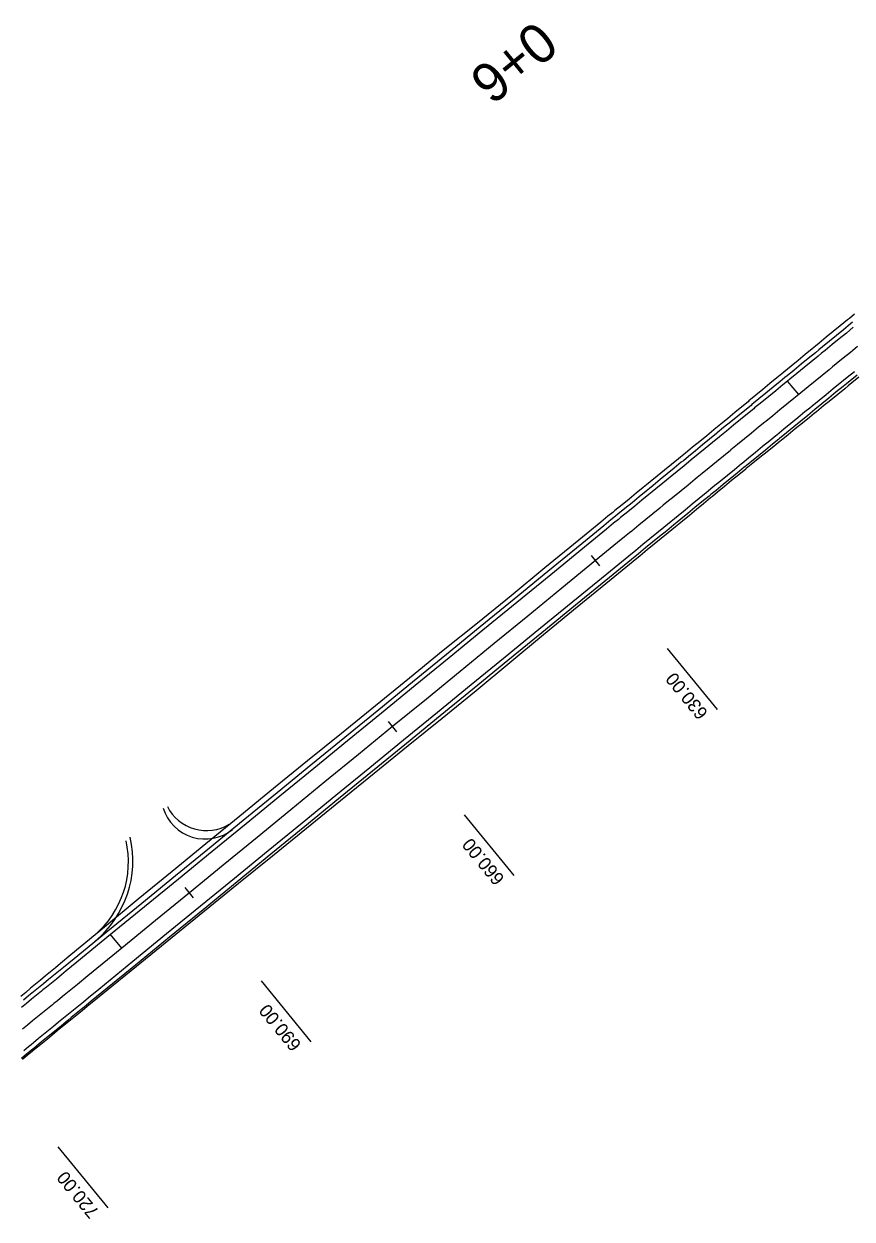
# Model space of a CAD drawing. Extents: x -550605 to -538780, y -1102367 to -1093705.
# Drawn here: x -547048.1 to -546953.4, y -1101076.3 to -1100939.6 of the extents above; entities that cross this region are included whole.
import ezdxf

# ---------------------------------------------------------------- set-up
doc = ezdxf.new("R2010")
doc.units = 0
for name, color, linetype in [('SIT - hrany vozovky', 7, 'Continuous'), ('SIT - oblouky - hrany', 7, 'Continuous'), ('SIT - oblouky - koruna', 7, 'Continuous'), ('SIT - osa cesty', 7, 'Continuous'), ('SIT - paty násypů', 7, 'Continuous'), ('SIT - staničení po 100m', 7, 'Continuous'), ('SIT - staničení po 30m', 7, 'Continuous')]:
    doc.layers.add(name, color=color, linetype=linetype)

msp = doc.modelspace()

# ---------------------------------------------------------------- linework, layer by layer
at = {"layer": 'SIT - hrany vozovky'}
for points in [[(-546953.35, -1100973.72), (-546953.57, -1100973.91), (-546954.38, -1100974.57), (-546955.19, -1100975.23), (-546955.99, -1100975.89), (-546956.8, -1100976.54), (-546957.22, -1100976.89), (-546957.6, -1100977.2), (-546958.41, -1100977.86), (-546959.22, -1100978.52), (-546960.02, -1100979.18), (-546960.83, -1100979.84), (-546961.09, -1100980.05), (-546961.64, -1100980.5), (-546962.44, -1100981.16), (-546963.25, -1100981.82), (-546964.06, -1100982.48), (-546964.86, -1100983.14), (-546964.96, -1100983.22), (-546965.67, -1100983.8), (-546966.47, -1100984.46), (-546967.28, -1100985.12), (-546968.09, -1100985.77), (-546968.83, -1100986.38), (-546968.89, -1100986.43), (-546969.7, -1100987.09), (-546970.51, -1100987.75), (-546971.31, -1100988.41), (-546972.12, -1100989.07), (-546972.7, -1100989.55), (-546972.93, -1100989.73), (-546973.73, -1100990.39), (-546974.54, -1100991.05), (-546975.34, -1100991.71), (-546976.15, -1100992.37), (-546976.57, -1100992.71), (-546976.96, -1100993.03), (-546977.76, -1100993.69), (-546978.57, -1100994.35), (-546979.38, -1100995), (-546980.18, -1100995.66), (-546980.44, -1100995.88), (-546980.99, -1100996.32), (-546981.8, -1100996.98), (-546984.31, -1100999.04), (-546988.18, -1101002.21), (-546992.05, -1101005.37), (-546995.93, -1101008.54), (-546999.8, -1101011.7), (-547003.67, -1101014.86), (-547007.54, -1101018.03), (-547011.41, -1101021.19), (-547015.28, -1101024.36), (-547019.15, -1101027.52), (-547023.02, -1101030.69), (-547026.89, -1101033.85), (-547030.76, -1101037.02), (-547034.63, -1101040.18), (-547038.51, -1101043.35), (-547042.38, -1101046.51), (-547043.58, -1101047.5), (-547044.15, -1101047.96), (-547044.72, -1101048.43), (-547045.29, -1101048.89), (-547045.86, -1101049.36), (-547046.25, -1101049.68), (-547046.43, -1101049.83), (-547047, -1101050.29), (-547047.57, -1101050.76), (-547048.14, -1101051.22)], [(-546953.26, -1100974.29), (-546954.06, -1100974.95), (-546954.87, -1100975.61), (-546955.68, -1100976.27), (-546956.48, -1100976.93), (-546956.9, -1100977.27), (-546957.29, -1100977.59), (-546958.09, -1100978.25), (-546958.9, -1100978.91), (-546959.71, -1100979.57), (-546960.51, -1100980.23), (-546960.77, -1100980.44), (-546961.32, -1100980.89), (-546962.13, -1100981.55), (-546962.93, -1100982.21), (-546963.74, -1100982.87), (-546964.55, -1100983.52), (-546964.64, -1100983.6), (-546965.35, -1100984.18), (-546966.16, -1100984.84), (-546966.96, -1100985.5), (-546967.77, -1100986.16), (-546968.51, -1100986.77), (-546968.58, -1100986.82), (-546969.38, -1100987.48), (-546970.19, -1100988.14), (-546971, -1100988.8), (-546971.8, -1100989.46), (-546972.38, -1100989.93), (-546972.61, -1100990.12), (-546973.42, -1100990.78), (-546974.22, -1100991.44), (-546975.03, -1100992.1), (-546975.83, -1100992.75), (-546976.25, -1100993.1), (-546976.64, -1100993.41), (-546977.45, -1100994.07), (-546978.25, -1100994.73), (-546979.06, -1100995.39), (-546979.87, -1100996.05), (-546980.13, -1100996.26), (-546980.67, -1100996.71), (-546981.48, -1100997.37), (-546984, -1100999.43), (-546987.87, -1101002.59), (-546991.74, -1101005.76), (-546995.61, -1101008.92), (-546999.48, -1101012.09), (-547003.35, -1101015.25), (-547007.22, -1101018.42), (-547011.09, -1101021.58), (-547014.96, -1101024.75), (-547018.83, -1101027.91), (-547022.71, -1101031.08), (-547026.58, -1101034.24), (-547030.45, -1101037.41), (-547034.32, -1101040.57), (-547038.19, -1101043.74), (-547042.06, -1101046.9), (-547043.27, -1101047.89), (-547043.83, -1101048.35), (-547044.4, -1101048.82), (-547044.97, -1101049.28), (-547045.54, -1101049.75), (-547045.93, -1101050.06), (-547046.11, -1101050.21), (-547046.68, -1101050.68), (-547047.25, -1101051.14), (-547047.82, -1101051.61), (-547048.39, -1101052.07)], [(-546953.14, -1100979.37), (-546953.95, -1100980.03), (-546954.37, -1100980.37), (-546954.76, -1100980.69), (-546955.56, -1100981.35), (-546956.37, -1100982.01), (-546957.18, -1100982.67), (-546957.98, -1100983.33), (-546958.24, -1100983.54), (-546958.79, -1100983.98), (-546959.59, -1100984.64), (-546960.4, -1100985.3), (-546961.21, -1100985.96), (-546962.01, -1100986.62), (-546962.11, -1100986.7), (-546962.82, -1100987.28), (-546963.63, -1100987.94), (-546964.43, -1100988.6), (-546965.24, -1100989.26), (-546965.98, -1100989.87), (-546966.05, -1100989.92), (-546966.85, -1100990.58), (-546967.66, -1100991.24), (-546968.46, -1100991.9), (-546969.27, -1100992.55), (-546969.85, -1100993.03), (-546970.08, -1100993.21), (-546970.88, -1100993.87), (-546971.69, -1100994.53), (-546972.5, -1100995.19), (-546973.3, -1100995.85), (-546973.72, -1100996.19), (-546974.11, -1100996.51), (-546974.92, -1100997.17), (-546975.72, -1100997.83), (-546976.53, -1100998.49), (-546977.33, -1100999.15), (-546977.59, -1100999.36), (-546978.14, -1100999.81), (-546978.95, -1101000.47), (-546981.46, -1101002.52), (-546985.34, -1101005.69), (-546989.21, -1101008.85), (-546993.08, -1101012.02), (-546996.95, -1101015.18), (-547000.82, -1101018.35), (-547004.69, -1101021.51), (-547008.56, -1101024.68), (-547012.43, -1101027.84), (-547016.3, -1101031.01), (-547020.17, -1101034.17), (-547024.04, -1101037.34), (-547027.92, -1101040.5), (-547031.79, -1101043.67), (-547035.66, -1101046.83), (-547039.53, -1101050), (-547040.73, -1101050.98), (-547041.3, -1101051.45), (-547041.87, -1101051.91), (-547042.44, -1101052.38), (-547043.01, -1101052.84), (-547043.4, -1101053.16), (-547043.58, -1101053.31), (-547044.15, -1101053.77), (-547044.72, -1101054.24), (-547045.29, -1101054.71), (-547045.86, -1101055.17), (-547046.43, -1101055.64), (-547047, -1101056.1), (-547047.27, -1101056.33), (-547047.57, -1101056.57), (-547048.13, -1101057.03)], [(-546952.83, -1100979.76), (-546953.63, -1100980.42), (-546954.05, -1100980.76), (-546954.44, -1100981.07), (-546955.25, -1100981.73), (-546956.05, -1100982.39), (-546956.86, -1100983.05), (-546957.67, -1100983.71), (-546957.92, -1100983.92), (-546958.47, -1100984.37), (-546959.28, -1100985.03), (-546960.08, -1100985.69), (-546960.89, -1100986.35), (-546961.7, -1100987.01), (-546961.79, -1100987.09), (-546962.5, -1100987.67), (-546963.31, -1100988.33), (-546964.12, -1100988.99), (-546964.92, -1100989.65), (-546965.66, -1100990.25), (-546965.73, -1100990.3), (-546966.54, -1100990.96), (-546967.34, -1100991.62), (-546968.15, -1100992.28), (-546968.95, -1100992.94), (-546969.54, -1100993.42), (-546969.76, -1100993.6), (-546970.57, -1100994.26), (-546971.37, -1100994.92), (-546972.18, -1100995.58), (-546972.99, -1100996.24), (-546973.41, -1100996.58), (-546973.79, -1100996.9), (-546974.6, -1100997.56), (-546975.41, -1100998.22), (-546976.21, -1100998.88), (-546977.02, -1100999.53), (-546977.28, -1100999.75), (-546977.82, -1101000.19), (-546978.63, -1101000.85), (-546981.15, -1101002.91), (-546985.02, -1101006.08), (-546988.89, -1101009.24), (-546992.76, -1101012.41), (-546996.63, -1101015.57), (-547000.5, -1101018.74), (-547004.37, -1101021.9), (-547008.24, -1101025.07), (-547012.12, -1101028.23), (-547015.99, -1101031.39), (-547019.86, -1101034.56), (-547023.73, -1101037.72), (-547027.6, -1101040.89), (-547031.47, -1101044.05), (-547035.34, -1101047.22), (-547039.21, -1101050.38), (-547040.42, -1101051.37), (-547040.99, -1101051.83), (-547041.56, -1101052.3), (-547042.12, -1101052.77), (-547042.69, -1101053.23), (-547043.08, -1101053.55), (-547043.26, -1101053.7), (-547043.83, -1101054.16), (-547044.4, -1101054.63), (-547044.97, -1101055.09), (-547045.54, -1101055.56), (-547046.11, -1101056.02), (-547046.68, -1101056.49), (-547046.95, -1101056.71), (-547047.25, -1101056.95), (-547047.82, -1101057.42), (-547048.39, -1101057.89)]]:
    msp.add_lwpolyline(points, dxfattribs=at)
at = {"layer": 'SIT - oblouky - hrany'}
for centre, radius, start, end in [((-547027.23, -1101026.85), 5, 206.5983, 301.3106), ((-547047.16, -1101035.44), 11, 310.5384, 12.8009)]:
    msp.add_arc(centre, radius, start, end, dxfattribs=at)
at = {"layer": 'SIT - oblouky - koruna'}
for centre, radius, start, end in [((-547027.39, -1101027.81), 5, 196.9978, 308.73), ((-547047.65, -1101035.29), 12, 309.9531, 12.8843)]:
    msp.add_arc(centre, radius, start, end, dxfattribs=at)
at = {"layer": 'SIT - osa cesty'}
msp.add_lwpolyline([(-546952.8, -1100976.5), (-546953.6, -1100977.16), (-546954.41, -1100977.82), (-546955.22, -1100978.48), (-546955.63, -1100978.82), (-546956.02, -1100979.14), (-546956.83, -1100979.8), (-546957.63, -1100980.46), (-546958.44, -1100981.12), (-546959.25, -1100981.78), (-546959.51, -1100981.99), (-546960.05, -1100982.44), (-546960.86, -1100983.1), (-546961.67, -1100983.75), (-546962.47, -1100984.41), (-546963.28, -1100985.07), (-546963.38, -1100985.15), (-546964.09, -1100985.73), (-546964.89, -1100986.39), (-546965.7, -1100987.05), (-546966.5, -1100987.71), (-546967.25, -1100988.32), (-546967.31, -1100988.37), (-546968.12, -1100989.03), (-546968.92, -1100989.69), (-546969.73, -1100990.35), (-546970.54, -1100991.01), (-546971.12, -1100991.48), (-546971.34, -1100991.67), (-546972.15, -1100992.33), (-546972.96, -1100992.98), (-546973.76, -1100993.64), (-546974.57, -1100994.3), (-546974.99, -1100994.65), (-546975.37, -1100994.96), (-546976.18, -1100995.62), (-546976.99, -1100996.28), (-546977.79, -1100996.94), (-546978.6, -1100997.6), (-546978.86, -1100997.81), (-546979.41, -1100998.26), (-546980.21, -1100998.92), (-546982.73, -1101000.98), (-546986.6, -1101004.14), (-546990.47, -1101007.31), (-546994.34, -1101010.47), (-546998.21, -1101013.64), (-547002.09, -1101016.8), (-547005.96, -1101019.96), (-547009.83, -1101023.13), (-547013.7, -1101026.29), (-547017.57, -1101029.46), (-547021.44, -1101032.62), (-547025.31, -1101035.79), (-547029.18, -1101038.95), (-547033.05, -1101042.12), (-547036.92, -1101045.28), (-547040.79, -1101048.45), (-547042, -1101049.43), (-547042.57, -1101049.9), (-547043.14, -1101050.36), (-547043.71, -1101050.83), (-547044.28, -1101051.3), (-547044.67, -1101051.61), (-547044.85, -1101051.76), (-547045.42, -1101052.23), (-547045.98, -1101052.69), (-547046.55, -1101053.16), (-547047.12, -1101053.62), (-547047.69, -1101054.09), (-547048.26, -1101054.55)], dxfattribs=at)
at = {"layer": 'SIT - paty násypů'}
for points in [[(-546953.14, -1100972.8), (-546953.71, -1100973.27), (-546953.94, -1100973.46), (-546954.75, -1100974.12), (-546955.55, -1100974.78), (-546956.36, -1100975.44), (-546957.16, -1100976.1), (-546957.58, -1100976.44), (-546957.97, -1100976.76), (-546958.77, -1100977.42), (-546959.58, -1100978.08), (-546960.38, -1100978.74), (-546961.19, -1100979.41), (-546961.44, -1100979.62), (-546961.99, -1100980.07), (-546962.79, -1100980.73), (-546963.6, -1100981.39), (-546964.4, -1100982.06), (-546965.2, -1100982.72), (-546965.3, -1100982.8), (-546966.01, -1100983.38), (-546966.81, -1100984.04), (-546967.61, -1100984.71), (-546968.42, -1100985.37), (-546969.16, -1100985.98), (-546969.22, -1100986.03), (-546970.03, -1100986.69), (-546970.83, -1100987.35), (-546971.64, -1100988.01), (-546972.45, -1100988.67), (-546973.03, -1100989.14), (-546973.26, -1100989.32), (-546974.07, -1100989.98), (-546974.87, -1100990.64), (-546975.68, -1100991.3), (-546976.49, -1100991.96), (-546976.91, -1100992.3), (-546977.29, -1100992.61), (-546978.1, -1100993.27), (-546978.91, -1100993.93), (-546979.71, -1100994.59), (-546980.52, -1100995.25), (-546980.78, -1100995.46), (-546981.33, -1100995.91), (-546982.13, -1100996.57), (-546984.65, -1100998.63), (-546988.52, -1101001.79), (-546992.37, -1101004.99), (-546996.25, -1101008.14), (-547000.15, -1101011.27), (-547004.03, -1101014.42), (-547007.91, -1101017.57), (-547011.79, -1101020.73), (-547015.67, -1101023.88), (-547019.55, -1101027.04), (-547023.42, -1101030.2), (-547027.29, -1101033.37), (-547031.17, -1101036.53), (-547035.03, -1101039.7), (-547038.89, -1101042.88), (-547042.74, -1101046.07), (-547043.94, -1101047.06), (-547044.51, -1101047.53), (-547045.07, -1101048), (-547045.64, -1101048.47), (-547046.2, -1101048.94), (-547046.59, -1101049.26), (-547046.77, -1101049.41), (-547047.34, -1101049.88), (-547047.9, -1101050.35), (-547048.47, -1101050.82)], [(-546952.62, -1100980.01), (-546953.43, -1100980.66), (-546953.85, -1100981), (-546954.24, -1100981.32), (-546955.05, -1100981.98), (-546955.85, -1100982.64), (-546956.66, -1100983.29), (-546957.47, -1100983.95), (-546957.73, -1100984.16), (-546958.28, -1100984.61), (-546959.09, -1100985.26), (-546959.9, -1100985.92), (-546960.71, -1100986.58), (-546961.51, -1100987.23), (-546961.61, -1100987.31), (-546962.32, -1100987.89), (-546963.13, -1100988.54), (-546963.94, -1100989.2), (-546964.75, -1100989.85), (-546965.5, -1100990.46), (-546965.56, -1100990.51), (-546966.37, -1100991.17), (-546967.18, -1100991.83), (-546967.98, -1100992.49), (-546968.78, -1100993.15), (-546969.36, -1100993.63), (-546969.59, -1100993.81), (-546970.39, -1100994.47), (-546971.2, -1100995.14), (-546972, -1100995.8), (-546972.81, -1100996.46), (-546973.23, -1100996.8), (-546973.61, -1100997.12), (-546974.42, -1100997.78), (-546975.22, -1100998.44), (-546976.03, -1100999.1), (-546976.83, -1100999.76), (-546977.09, -1100999.98), (-546977.64, -1101000.42), (-546978.44, -1101001.08), (-546980.96, -1101003.14), (-546984.83, -1101006.31), (-546988.69, -1101009.48), (-546992.54, -1101012.68), (-546996.39, -1101015.87), (-547000.27, -1101019.02), (-547004.16, -1101022.17), (-547008.04, -1101025.31), (-547011.92, -1101028.46), (-547015.81, -1101031.61), (-547019.69, -1101034.76), (-547023.58, -1101037.91), (-547027.46, -1101041.06), (-547031.35, -1101044.21), (-547035.22, -1101047.37), (-547039.09, -1101050.53), (-547040.3, -1101051.51), (-547040.87, -1101051.98), (-547041.44, -1101052.44), (-547042.01, -1101052.91), (-547042.58, -1101053.37), (-547042.97, -1101053.69), (-547043.15, -1101053.84), (-547043.72, -1101054.3), (-547044.29, -1101054.76), (-547044.86, -1101055.23), (-547045.43, -1101055.69), (-547046, -1101056.16), (-547046.57, -1101056.62), (-547046.85, -1101056.84), (-547047.14, -1101057.08), (-547047.72, -1101057.55), (-547048.29, -1101058.01)]]:
    msp.add_lwpolyline(points, dxfattribs=at)
at = {"layer": 'SIT - staničení po 100m'}
for points in [[(-546959.51, -1100981.99), (-546960.77, -1100980.44)], [(-547036.92, -1101045.28), (-547038.19, -1101043.74)]]:
    msp.add_lwpolyline(points, dxfattribs=at)
at = {"layer": 'SIT - staničení po 30m'}
for points in [[(-546982.26, -1101001.56), (-546983.21, -1101000.4)], [(-546968.81, -1101018.01), (-546974.5, -1101011.04)], [(-547005.48, -1101020.55), (-547006.43, -1101019.38)], [(-546992.03, -1101037), (-546997.73, -1101030.03)], [(-547028.71, -1101039.53), (-547029.66, -1101038.37)], [(-547015.26, -1101055.99), (-547020.95, -1101049.02)], [(-547038.48, -1101074.97), (-547044.18, -1101068.01)]]:
    msp.add_lwpolyline(points, dxfattribs=at)

# ---------------------------------------------------------------- texts
at = {"layer": 'SIT - staničení po 100m'}
msp.add_text('0+6', height=4.5, rotation=219.269, dxfattribs=at).set_placement((-546989.53, -1100939.05))
at = {"layer": 'SIT - staničení po 30m'}
for s, p in [('630.00', (-546969.8, -1101018.37)), ('660.00', (-546993.07, -1101037.31)), ('690.00', (-547016.3, -1101056.29)), ('720.00', (-547039.42, -1101075.4))]:
    msp.add_text(s, height=1.5, rotation=129.269, dxfattribs=at).set_placement(p)

doc.saveas('drawing.dxf')
